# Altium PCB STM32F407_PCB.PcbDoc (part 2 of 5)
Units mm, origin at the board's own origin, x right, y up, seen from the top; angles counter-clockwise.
Board outline 100.27 x 100.27 mm, 2 copper layers (Top Layer, Bottom Layer); 134 components, 132 nets, 659 pads, 288 vias.
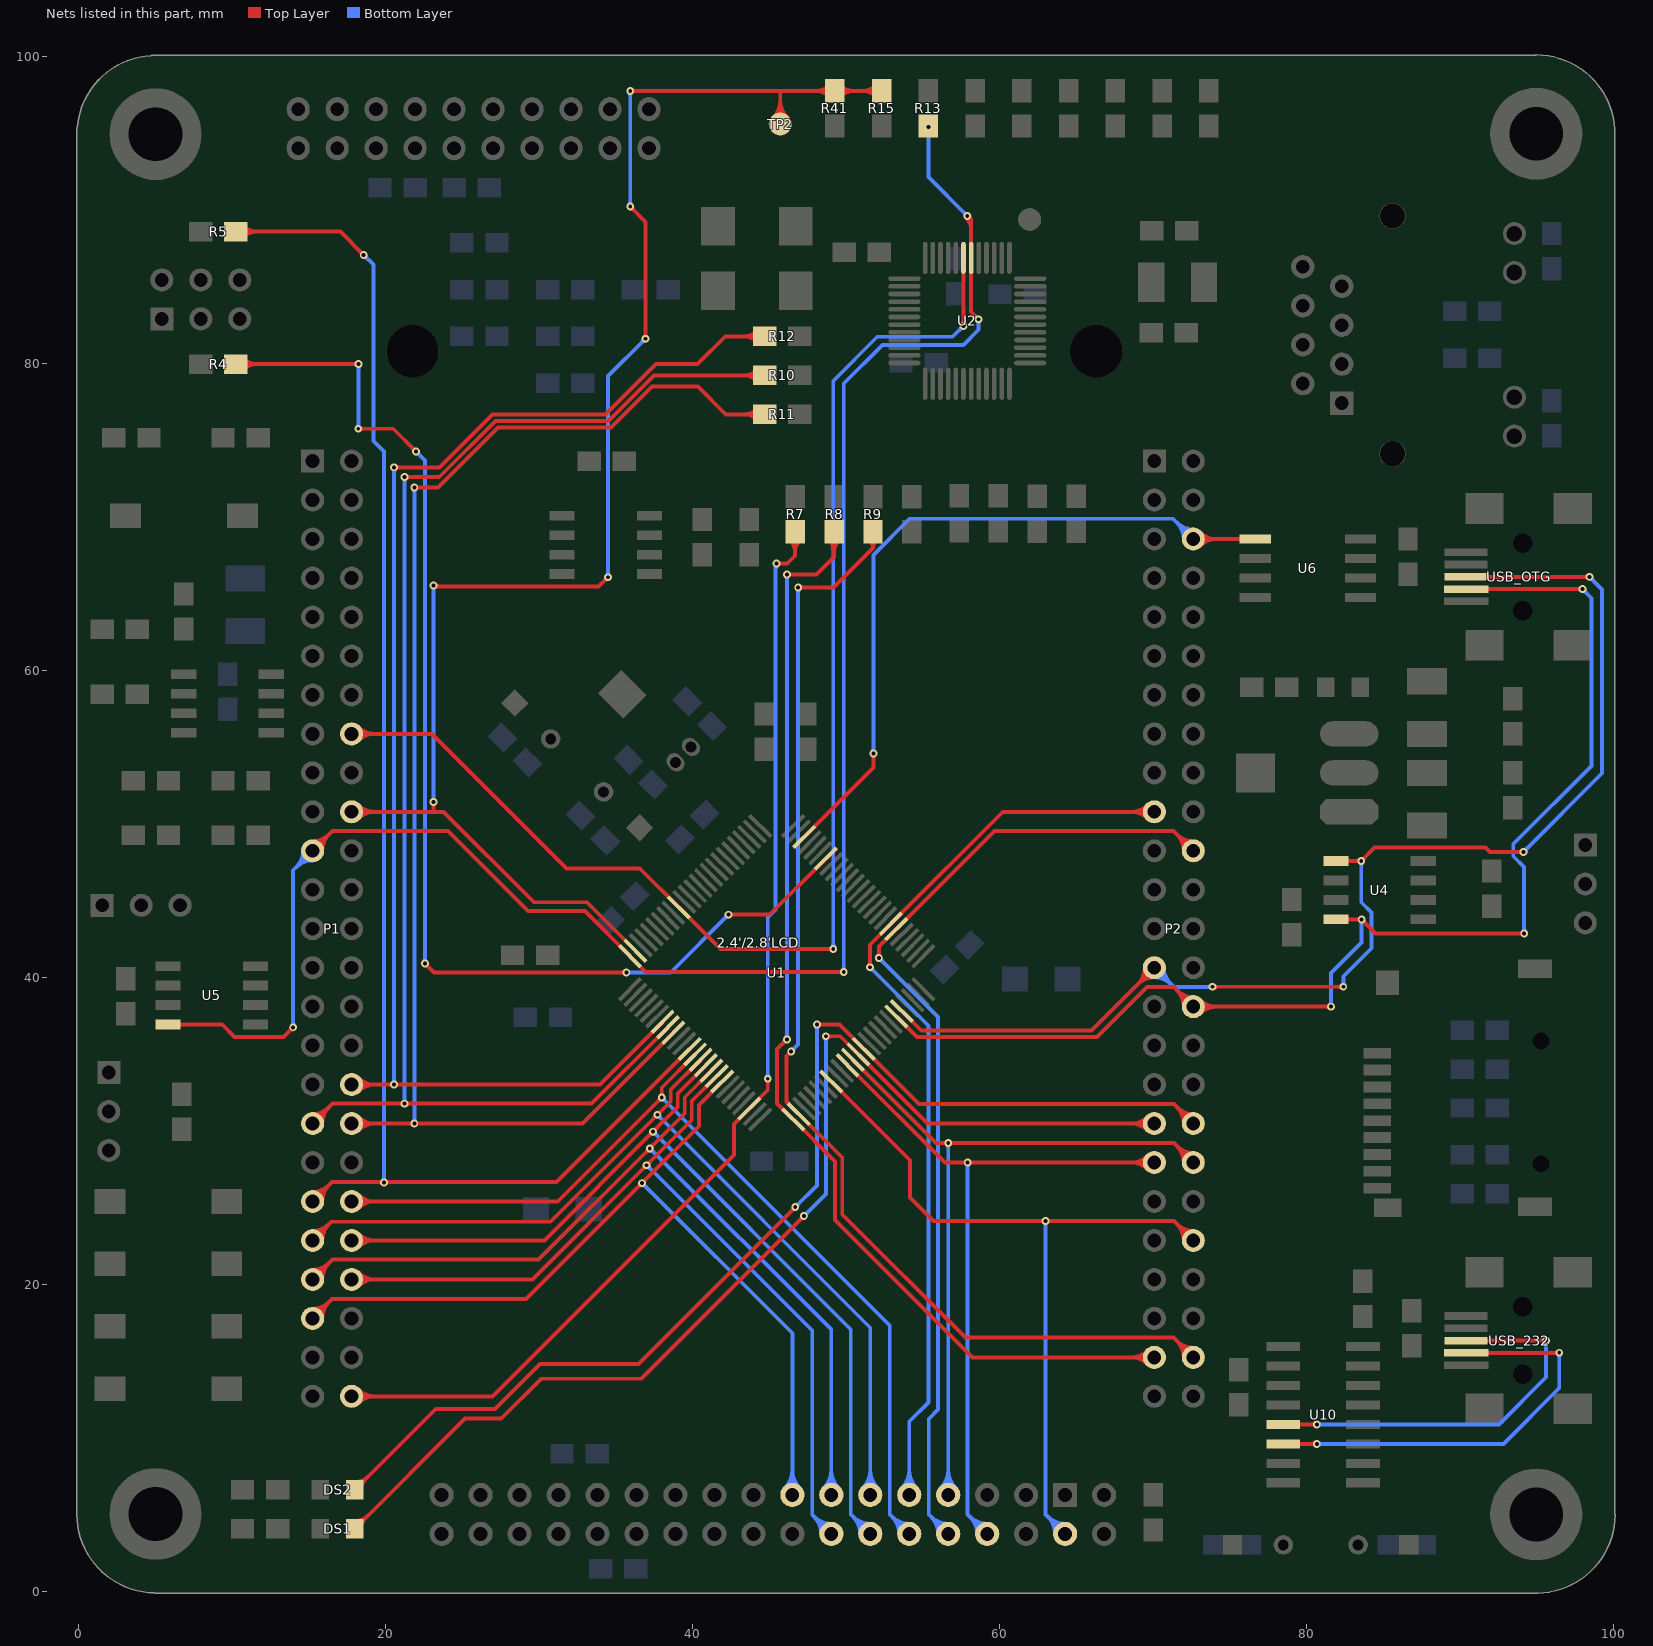
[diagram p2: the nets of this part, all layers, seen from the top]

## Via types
v1: diameter 0.508, hole 0.254, Top Layer to Bottom Layer, 288 vias

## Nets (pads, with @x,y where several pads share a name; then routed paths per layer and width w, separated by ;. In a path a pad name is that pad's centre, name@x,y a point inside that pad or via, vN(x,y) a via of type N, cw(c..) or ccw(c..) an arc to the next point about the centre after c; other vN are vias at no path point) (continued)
BOOT0: R4.2 U1.94 | length 94.7
  Top Layer w0.254: R4.2@10.236,79.983 v1(18.237,79.983) ; v1(18.212,75.768) 20.498,75.768 v1(21.984,74.282) ; v1(22.555,40.919) 23.139,40.335 v1(35.687,40.335) ; v1(42.342,44.094) 45.033,44.094 U1.94@48.691,47.752 ; 11.59,79.983 cw(c11.59,81.209) 10.722,80.342 ccw(c11.59,81.209) 11.59,79.983 ; 11.59,79.983 ccw(c11.59,78.757) 10.722,79.624 cw(c11.59,78.757) 11.59,79.983 ; 17.931,79.983 cw(c17.931,79.676) 18.147,79.893 ccw(c17.931,79.676) 17.931,79.983 ; 17.931,79.983 ccw(c17.931,80.29) 18.147,80.073 cw(c17.931,80.29) 17.931,79.983 ; 18.518,75.768 cw(c18.518,76.075) 18.302,75.858 ccw(c18.518,76.075) 18.518,75.768 ; 18.518,75.768 ccw(c18.518,75.462) 18.302,75.678 cw(c18.518,75.462) 18.518,75.768 ; 21.767,74.499 cw(c21.55,74.282) 21.857,74.282 ccw(c21.55,74.282) 21.767,74.499 ; 21.767,74.499 ccw(c21.984,74.716) 21.984,74.409 cw(c21.984,74.716) 21.767,74.499 ; 22.772,40.703 cw(c22.989,40.919) 22.682,40.919 ccw(c22.989,40.919) 22.772,40.703 ; 22.772,40.703 ccw(c22.555,40.486) 22.555,40.792 cw(c22.555,40.486) 22.772,40.703 ; 35.38,40.335 cw(c35.38,40.029) 35.597,40.245 ccw(c35.38,40.029) 35.38,40.335 ; 35.38,40.335 ccw(c35.38,40.642) 35.597,40.425 cw(c35.38,40.642) 35.38,40.335 ; 42.648,44.094 cw(c42.648,44.401) 42.432,44.184 ccw(c42.648,44.401) 42.648,44.094 ; 42.648,44.094 ccw(c42.648,43.788) 42.432,44.005 cw(c42.648,43.788) 42.648,44.094
  Bottom Layer w0.254: v1(18.212,75.768) 18.237,75.794 v1(18.237,79.983) ; v1@21.971,74.295 v1(21.984,74.282) 22.555,73.711 v1(22.555,40.919) ; v1(35.687,40.335) 38.583,40.335 v1(42.342,44.094) ; 18.237,79.676 cw(c18.544,79.676) 18.327,79.893 ccw(c18.544,79.676) 18.237,79.676 ; 18.237,79.676 ccw(c17.931,79.676) 18.147,79.893 cw(c17.931,79.676) 18.237,79.676 ; 22.201,74.065 cw(c22.417,74.282) 22.111,74.282 ccw(c22.417,74.282) 22.201,74.065 ; 22.201,74.065 ccw(c21.984,73.849) 21.984,74.155 cw(c21.984,73.849) 22.201,74.065 ; 22.555,41.226 cw(c22.249,41.226) 22.465,41.009 ccw(c22.249,41.226) 22.555,41.226 ; 22.555,41.226 ccw(c22.862,41.226) 22.645,41.009 cw(c22.862,41.226) 22.555,41.226 ; 35.994,40.335 cw(c35.994,40.642) 35.777,40.425 ccw(c35.994,40.642) 35.994,40.335 ; 35.994,40.335 ccw(c35.994,40.029) 35.777,40.245 cw(c35.994,40.029) 35.994,40.335 ; 42.125,43.878 cw(c42.342,43.661) 42.342,43.967 ccw(c42.342,43.661) 42.125,43.878 ; 42.125,43.878 ccw(c41.908,44.094) 42.215,44.094 cw(c41.908,44.094) 42.125,43.878 ; v1@18.122,75.858 ccw(c17.844,76.136) 18.237,76.136 cw(c17.844,76.136) v1@18.122,75.858
BOOT1: P1.39 R5.2 U1.37 | length 114.2
  Top Layer w0.254: R5.2@10.236,88.619 17.045,88.619 v1(18.567,87.097) ; P1.39@15.24,25.4 16.51,26.67 31.145,26.67 U1.37@39.817,35.342 ; 11.59,88.619 cw(c11.59,89.845) 10.722,88.978 ccw(c11.59,89.845) 11.59,88.619 ; 11.59,88.619 ccw(c11.59,87.393) 10.722,88.26 cw(c11.59,87.393) 11.59,88.619 ; 15.87,26.03 cw(c15.24,26.66) 15.24,25.769 ccw(c15.24,26.66) 15.87,26.03 ; 15.87,26.03 ccw(c16.5,25.4) 15.609,25.4 cw(c16.5,25.4) 15.87,26.03 ; 16.304,26.464 cw(c15.24,27.527) 15.24,26.023 ccw(c15.24,27.527) 16.304,26.464 ; 16.304,26.464 ccw(c17.367,25.4) 15.863,25.4 cw(c17.367,25.4) 16.304,26.464 ; 18.351,87.313 cw(c18.134,87.097) 18.44,87.097 ccw(c18.134,87.097) 18.351,87.313 ; 18.351,87.313 ccw(c18.567,87.53) 18.567,87.224 cw(c18.567,87.53) 18.351,87.313 ; 19.52,26.67 cw(c19.52,26.277) 19.798,26.555 ccw(c19.52,26.277) 19.52,26.67 ; v1@19.978,26.555 cw(c20.256,26.277) 20.256,26.67 ccw(c20.256,26.277) v1@19.978,26.555
  Bottom Layer w0.254: v1(18.567,87.097) 19.202,86.462 19.202,74.981 19.888,74.295 v1(19.888,26.645) ; 18.784,86.88 cw(c19.001,87.097) 18.694,87.097 ccw(c19.001,87.097) 18.784,86.88 ; 18.784,86.88 ccw(c18.567,86.663) 18.567,86.97 cw(c18.567,86.663) 18.784,86.88 ; 19.888,26.951 cw(c19.582,26.951) 19.798,26.734 ccw(c19.582,26.951) 19.888,26.951 ; 19.888,26.951 ccw(c20.195,26.951) 19.978,26.734 cw(c20.195,26.951) 19.888,26.951
CAN_RX: P2.30 U1.70 U4.4 USB_OTG.2 | length 108.7
  Top Layer w0.254: U1.70@53.287,37.464 54.632,36.119 66.37,36.119 69.621,39.37 71.374,39.37 P2.30@72.644,38.1 v1(81.61,38.1) ; U4.4@81.94,43.79 v1(83.617,43.79) 84.531,42.875 v1(94.209,42.875) ; USB_OTG.2@90.424,65.316 v1(98.006,65.316) ; 71.58,39.164 cw(c70.517,38.1) 72.021,38.1 ccw(c70.517,38.1) 71.58,39.164 ; 71.58,39.164 ccw(c72.644,40.227) 72.644,38.723 cw(c72.644,40.227) 71.58,39.164 ; 72.014,38.73 cw(c71.384,38.1) 72.275,38.1 ccw(c71.384,38.1) 72.014,38.73 ; 72.014,38.73 ccw(c72.644,39.36) 72.644,38.469 cw(c72.644,39.36) 72.014,38.73 ; 73.535,38.1 cw(c73.535,38.991) 72.905,38.361 ccw(c73.535,38.991) 73.535,38.1 ; 73.535,38.1 ccw(c73.535,37.209) 72.905,37.839 cw(c73.535,37.209) 73.535,38.1 ; 74.148,38.1 cw(c74.148,39.604) 73.085,38.541 ccw(c74.148,39.604) 74.148,38.1 ; 74.148,38.1 ccw(c74.148,36.596) 73.085,37.659 cw(c74.148,36.596) 74.148,38.1 ; 81.304,38.1 cw(c81.304,37.793) 81.52,38.01 ccw(c81.304,37.793) 81.304,38.1 ; 81.304,38.1 ccw(c81.304,38.407) 81.52,38.19 cw(c81.304,38.407) 81.304,38.1 ; 82.908,43.79 cw(c82.908,44.25) 82.583,43.924 ccw(c82.908,44.25) 82.908,43.79 ; 82.908,43.79 ccw(c82.908,43.33) 82.583,43.655 cw(c82.908,43.33) 82.908,43.79 ; 83.31,43.79 cw(c83.31,43.483) 83.527,43.7 ccw(c83.31,43.483) 83.31,43.79 ; 83.31,43.79 ccw(c83.31,44.096) 83.527,43.879 cw(c83.31,44.096) 83.31,43.79 ; 83.834,43.573 cw(c84.05,43.79) 83.744,43.79 ccw(c84.05,43.79) 83.834,43.573 ; 83.834,43.573 ccw(c83.617,43.356) 83.617,43.663 cw(c83.617,43.356) 83.834,43.573 ; 91.921,65.316 cw(c91.921,65.613) 91.711,65.403 ccw(c91.921,65.613) 91.921,65.316 ; 91.921,65.316 ccw(c91.921,65.019) 91.711,65.229 cw(c91.921,65.019) 91.921,65.316 ; 93.902,42.875 cw(c93.902,42.569) 94.119,42.785 ccw(c93.902,42.569) 93.902,42.875 ; 93.902,42.875 ccw(c93.902,43.182) 94.119,42.965 cw(c93.902,43.182) 93.902,42.875 ; 97.699,65.316 cw(c97.699,65.009) 97.916,65.226 ccw(c97.699,65.009) 97.699,65.316 ; 97.699,65.316 ccw(c97.699,65.623) 97.916,65.406 cw(c97.699,65.623) 97.699,65.316
  Bottom Layer w0.254: v1(81.61,38.1) 81.61,40.284 83.617,42.291 v1(83.617,43.79) ; v1(94.209,42.875) 94.209,47.193 93.497,47.904 93.497,48.692 98.603,53.797 98.603,64.719 v1(98.006,65.316) ; 81.61,38.407 cw(c81.304,38.407) 81.52,38.19 ccw(c81.304,38.407) 81.61,38.407 ; 81.61,38.407 ccw(c81.917,38.407) 81.7,38.19 cw(c81.917,38.407) 81.61,38.407 ; 83.617,43.483 cw(c83.923,43.483) 83.707,43.7 ccw(c83.923,43.483) 83.617,43.483 ; 83.617,43.483 ccw(c83.31,43.483) 83.527,43.7 cw(c83.31,43.483) 83.617,43.483 ; 94.209,43.182 cw(c93.902,43.182) 94.119,42.965 ccw(c93.902,43.182) 94.209,43.182 ; 94.209,43.182 ccw(c94.515,43.182) 94.298,42.965 cw(c94.515,43.182) 94.209,43.182 ; 98.223,65.099 cw(c98.439,65.316) 98.133,65.316 ccw(c98.439,65.316) 98.223,65.099 ; 98.223,65.099 ccw(c98.006,64.882) 98.006,65.189 cw(c98.006,64.882) 98.223,65.099
CAN_TX: P2.27 U1.71 U4.1 USB_OTG.3 | length 109.6
  Top Layer w0.254: U1.71@53.641,37.817 54.907,36.551 66.015,36.551 P2.27@70.104,40.64 ; v1(73.889,39.395) v1(82.423,39.395) ; U4.1@81.94,47.6 v1(83.591,47.6) 84.455,48.463 91.694,48.463 91.973,48.184 v1(94.158,48.184) ; USB_OTG.3@90.424,66.116 v1(98.476,66.116) ; 69.04,39.576 cw(c70.104,38.513) 70.104,40.017 ccw(c70.104,38.513) 69.04,39.576 ; 69.04,39.576 ccw(c67.977,40.64) 69.481,40.64 cw(c67.977,40.64) 69.04,39.576 ; 69.474,40.01 cw(c70.104,39.38) 70.104,40.271 ccw(c70.104,39.38) 69.474,40.01 ; 69.474,40.01 ccw(c68.844,40.64) 69.735,40.64 cw(c68.844,40.64) 69.474,40.01 ; 74.195,39.395 cw(c74.195,39.702) 73.978,39.485 ccw(c74.195,39.702) 74.195,39.395 ; 74.195,39.395 ccw(c74.195,39.089) 73.978,39.306 cw(c74.195,39.089) 74.195,39.395 ; 82.116,39.395 cw(c82.116,39.089) 82.333,39.306 ccw(c82.116,39.089) 82.116,39.395 ; 82.116,39.395 ccw(c82.116,39.702) 82.333,39.485 cw(c82.116,39.702) 82.116,39.395 ; 82.908,47.6 cw(c82.908,48.06) 82.583,47.734 ccw(c82.908,48.06) 82.908,47.6 ; 82.908,47.6 ccw(c82.908,47.14) 82.583,47.465 cw(c82.908,47.14) 82.908,47.6 ; 83.285,47.6 cw(c83.285,47.293) 83.502,47.51 ccw(c83.285,47.293) 83.285,47.6 ; 83.285,47.6 ccw(c83.285,47.906) 83.502,47.689 cw(c83.285,47.906) 83.285,47.6 ; 83.808,47.816 cw(c83.591,48.033) 83.591,47.727 ccw(c83.591,48.033) 83.808,47.816 ; 83.808,47.816 ccw(c84.025,47.6) 83.718,47.6 cw(c84.025,47.6) 83.808,47.816 ; 91.871,66.116 cw(c91.871,66.413) 91.661,66.203 ccw(c91.871,66.413) 91.871,66.116 ; 91.871,66.116 ccw(c91.871,65.819) 91.661,66.029 cw(c91.871,65.819) 91.871,66.116 ; 93.851,48.184 cw(c93.851,47.877) 94.068,48.094 ccw(c93.851,47.877) 93.851,48.184 ; 93.851,48.184 ccw(c93.851,48.49) 94.068,48.274 cw(c93.851,48.49) 93.851,48.184 ; 98.169,66.116 cw(c98.169,65.809) 98.386,66.026 ccw(c98.169,65.809) 98.169,66.116 ; 98.169,66.116 ccw(c98.169,66.423) 98.386,66.206 cw(c98.169,66.423) 98.169,66.116
  Bottom Layer w0.254: P2.27@70.104,40.64 71.374,39.37 73.863,39.37 v1(73.889,39.395) ; v1(82.423,39.395) 82.423,40.081 84.252,41.91 84.252,44.247 83.591,44.907 v1(83.591,47.6) ; v1(94.158,48.184) 99.289,53.315 99.289,65.303 v1(98.476,66.116) ; 70.734,40.01 cw(c71.364,40.64) 70.473,40.64 ccw(c71.364,40.64) 70.734,40.01 ; 70.734,40.01 ccw(c70.104,39.38) 70.104,40.271 cw(c70.104,39.38) 70.734,40.01 ; 71.168,39.576 cw(c72.231,40.64) 70.727,40.64 ccw(c72.231,40.64) 71.168,39.576 ; 71.168,39.576 ccw(c70.104,38.513) 70.104,40.017 cw(c70.104,38.513) 71.168,39.576 ; 82.423,39.702 cw(c82.116,39.702) 82.333,39.485 ccw(c82.116,39.702) 82.423,39.702 ; 82.423,39.702 ccw(c82.73,39.702) 82.513,39.485 cw(c82.73,39.702) 82.423,39.702 ; 83.591,47.293 cw(c83.898,47.293) 83.681,47.51 ccw(c83.898,47.293) 83.591,47.293 ; 83.591,47.293 ccw(c83.285,47.293) 83.502,47.51 cw(c83.285,47.293) 83.591,47.293 ; 94.375,48.401 cw(c94.158,48.617) 94.158,48.311 ccw(c94.158,48.617) 94.375,48.401 ; 94.375,48.401 ccw(c94.591,48.184) 94.285,48.184 cw(c94.591,48.184) 94.375,48.401 ; 98.692,65.899 cw(c98.909,66.116) 98.603,66.116 ccw(c98.909,66.116) 98.692,65.899 ; 98.692,65.899 ccw(c98.476,65.682) 98.476,65.989 cw(c98.476,65.682) 98.692,65.899 ; 73.521,39.37 ccw(c73.521,39.763) 73.799,39.485 cw(c73.521,39.763) 73.521,39.37
CH340_D+: U10.5 USB_232.3 | length 32.1
  Top Layer w0.254: U10.5@78.502,10.871 v1(80.696,10.871) ; USB_232.3@90.424,16.332 v1(95.631,16.332) ; 79.72,10.871 cw(c79.72,11.289) 79.425,10.994 ccw(c79.72,11.289) 79.72,10.871 ; 79.72,10.871 ccw(c79.72,10.454) 79.425,10.749 cw(c79.72,10.454) 79.72,10.871 ; 80.389,10.871 cw(c80.389,10.565) 80.606,10.781 ccw(c80.389,10.565) 80.389,10.871 ; 80.389,10.871 ccw(c80.389,11.178) 80.606,10.961 cw(c80.389,11.178) 80.389,10.871 ; 91.871,16.332 cw(c91.871,16.629) 91.661,16.419 ccw(c91.871,16.629) 91.871,16.332 ; 91.871,16.332 ccw(c91.871,16.035) 91.661,16.245 cw(c91.871,16.035) 91.871,16.332 ; 95.325,16.332 cw(c95.325,16.025) 95.541,16.242 ccw(c95.325,16.025) 95.325,16.332 ; 95.325,16.332 ccw(c95.325,16.639) 95.541,16.422 cw(c95.325,16.639) 95.325,16.332
  Bottom Layer w0.254: v1(80.696,10.871) 92.558,10.871 95.631,13.945 v1(95.631,16.332) ; 81.002,10.871 cw(c81.002,11.178) 80.786,10.961 ccw(c81.002,11.178) 81.002,10.871 ; 81.002,10.871 ccw(c81.002,10.565) 80.786,10.781 cw(c81.002,10.565) 81.002,10.871 ; 95.631,16.025 cw(c95.938,16.025) 95.721,16.242 ccw(c95.938,16.025) 95.631,16.025 ; 95.631,16.025 ccw(c95.325,16.025) 95.541,16.242 cw(c95.325,16.025) 95.631,16.025
CH340_D-: U10.6 USB_232.2 | length 34
  Top Layer w0.254: U10.6@78.502,9.601 v1(80.696,9.601) ; USB_232.2@90.424,15.532 v1@96.495,15.532 ; 79.72,9.601 cw(c79.72,10.019) 79.425,9.724 ccw(c79.72,10.019) 79.72,9.601 ; 79.72,9.601 ccw(c79.72,9.184) 79.425,9.479 cw(c79.72,9.184) 79.72,9.601 ; 80.389,9.601 cw(c80.389,9.295) 80.606,9.511 ccw(c80.389,9.295) 80.389,9.601 ; 80.389,9.601 ccw(c80.389,9.908) 80.606,9.691 cw(c80.389,9.908) 80.389,9.601 ; 91.921,15.532 cw(c91.921,15.829) 91.711,15.619 ccw(c91.921,15.829) 91.921,15.532 ; 91.921,15.532 ccw(c91.921,15.235) 91.711,15.445 cw(c91.921,15.235) 91.921,15.532 ; 96.157,15.532 ccw(c96.157,15.882) 96.405,15.635 cw(c96.157,15.882) 96.157,15.532 ; 96.219,15.532 cw(c96.219,15.269) 96.405,15.455 ccw(c96.219,15.269) 96.219,15.532
  Bottom Layer w0.254: v1(80.696,9.601) 92.862,9.601 96.495,13.233 v1(96.495,15.545) ; 81.002,9.601 cw(c81.002,9.908) 80.786,9.691 ccw(c81.002,9.908) 81.002,9.601 ; 81.002,9.601 ccw(c81.002,9.295) 80.786,9.511 cw(c81.002,9.295) 81.002,9.601 ; 96.495,15.238 cw(c96.801,15.238) 96.584,15.455 ccw(c96.801,15.238) 96.495,15.238 ; 96.495,15.238 ccw(c96.188,15.238) 96.405,15.455 cw(c96.188,15.238) 96.495,15.238
DS1: DS1.2 P2.35 U1.63 | length 88.6
  Top Layer w0.254: DS1.2@17.983,4.064 25.171,11.252 27.534,11.252 30.124,13.843 36.652,13.843 v1(47.257,24.447) ; v1(48.692,36.17) 49.632,36.17 U1.63@50.812,34.989 55.321,30.48 P2.35@70.104,30.48 ; 47.04,24.231 cw(c47.257,24.014) 47.257,24.32 ccw(c47.257,24.014) 47.04,24.231 ; 47.04,24.231 ccw(c46.823,24.447) 47.13,24.447 cw(c46.823,24.447) 47.04,24.231 ; 48.998,36.17 cw(c48.998,36.476) 48.782,36.259 ccw(c48.998,36.476) 48.998,36.17 ; 48.998,36.17 ccw(c48.998,35.863) 48.782,36.08 cw(c48.998,35.863) 48.998,36.17 ; 68.6,30.48 cw(c68.6,28.976) 69.663,30.039 ccw(c68.6,28.976) 68.6,30.48 ; 68.6,30.48 ccw(c68.6,31.984) 69.663,30.921 cw(c68.6,31.984) 68.6,30.48 ; 69.213,30.48 cw(c69.213,29.589) 69.843,30.219 ccw(c69.213,29.589) 69.213,30.48 ; 69.213,30.48 ccw(c69.213,31.371) 69.843,30.741 cw(c69.213,31.371) 69.213,30.48 ; DS1.2@17.983,4.572 ccw(c17.983,5.798) 18.85,4.931 cw(c17.983,5.798) DS1.2@17.983,4.572 ; DS1.2@18.428,4.127 cw(c19.348,4.127) 18.697,4.778 ccw(c19.348,4.127) DS1.2@18.428,4.127
  Bottom Layer w0.254: v1(47.257,24.447) 48.692,25.883 v1(48.692,36.17) ; 47.474,24.664 cw(c47.257,24.881) 47.257,24.575 ccw(c47.257,24.881) 47.474,24.664 ; 47.474,24.664 ccw(c47.69,24.447) 47.384,24.447 cw(c47.69,24.447) 47.474,24.664 ; 48.692,35.863 cw(c48.998,35.863) 48.782,36.08 ccw(c48.998,35.863) 48.692,35.863 ; 48.692,35.863 ccw(c48.385,35.863) 48.602,36.08 cw(c48.385,35.863) 48.692,35.863
DS2: DS2.2 P2.36 U1.64 | length 90.8
  Top Layer w0.254: DS2.2@17.983,6.604 23.266,11.887 27.127,11.887 30.048,14.808 36.474,14.808 v1@46.711,25.044 ; v1(48.108,36.932) 49.577,36.932 U1.64@51.166,35.342 54.758,31.75 71.374,31.75 P2.36@72.644,30.48 ; 46.481,24.815 cw(c46.698,24.598) 46.698,24.905 ccw(c46.698,24.598) 46.481,24.815 ; 46.481,24.815 ccw(c46.264,25.032) 46.571,25.032 cw(c46.264,25.032) 46.481,24.815 ; 48.414,36.932 cw(c48.414,37.238) 48.197,37.021 ccw(c48.414,37.238) 48.414,36.932 ; 48.414,36.932 ccw(c48.414,36.625) 48.197,36.842 cw(c48.414,36.625) 48.414,36.932 ; 71.58,31.544 cw(c70.517,30.48) 72.021,30.48 ccw(c70.517,30.48) 71.58,31.544 ; 71.58,31.544 ccw(c72.644,32.607) 72.644,31.103 cw(c72.644,32.607) 71.58,31.544 ; 72.014,31.11 cw(c71.384,30.48) 72.275,30.48 ccw(c71.384,30.48) 72.014,31.11 ; 72.014,31.11 ccw(c72.644,31.74) 72.644,30.849 cw(c72.644,31.74) 72.014,31.11 ; DS2.2@17.983,7.112 ccw(c17.983,8.338) 18.85,7.471 cw(c17.983,8.338) DS2.2@17.983,7.112 ; DS2.2@18.428,6.667 cw(c19.348,6.667) 18.697,7.318 ccw(c19.348,6.667) DS2.2@18.428,6.667
  Bottom Layer w0.254: v1(46.698,25.032) 48.108,26.441 v1(48.108,36.932) ; 46.915,25.249 cw(c46.698,25.465) 46.698,25.159 ccw(c46.698,25.465) 46.915,25.249 ; 46.915,25.249 ccw(c47.132,25.032) 46.825,25.032 cw(c47.132,25.032) 46.915,25.249 ; 48.108,36.625 cw(c48.414,36.625) 48.197,36.842 ccw(c48.414,36.625) 48.108,36.625 ; 48.108,36.625 ccw(c47.801,36.625) 48.018,36.842 cw(c47.801,36.625) 48.108,36.625
ETH_MDC: P1.16 U1.16 U2.31 | length 100
  Top Layer w0.254: P1.16@17.78,55.88 23.012,55.88 31.775,47.117 36.563,47.117 U1.16@39.11,44.57 41.821,41.859 v1(49.174,41.859) ; v1(57.658,82.474) 57.662,82.478 U2.31@57.662,86.904 ; 18.671,55.88 cw(c18.671,56.771) 18.041,56.141 ccw(c18.671,56.771) 18.671,55.88 ; 18.671,55.88 ccw(c18.671,54.989) 18.041,55.619 cw(c18.671,54.989) 18.671,55.88 ; 19.284,55.88 cw(c19.284,57.384) 18.221,56.321 ccw(c19.284,57.384) 19.284,55.88 ; 19.284,55.88 ccw(c19.284,54.376) 18.221,55.439 cw(c19.284,54.376) 19.284,55.88 ; 48.868,41.859 cw(c48.868,41.553) 49.085,41.769 ccw(c48.868,41.553) 48.868,41.859 ; 48.868,41.859 ccw(c48.868,42.166) 49.085,41.949 cw(c48.868,42.166) 48.868,41.859 ; v1@57.568,82.564 ccw(c57.342,82.79) 57.662,82.79 cw(c57.342,82.79) v1@57.568,82.564 ; 57.662,82.771 ccw(c57.955,82.771) 57.748,82.564 cw(c57.955,82.771) 57.662,82.771
  Bottom Layer w0.254: v1(49.174,41.859) 49.174,78.892 52.045,81.763 56.947,81.763 v1(57.658,82.474) ; 49.174,42.166 cw(c48.868,42.166) 49.085,41.949 ccw(c48.868,42.166) 49.174,42.166 ; 49.174,42.166 ccw(c49.481,42.166) 49.264,41.949 cw(c49.481,42.166) 49.174,42.166 ; 57.441,82.257 cw(c57.658,82.04) 57.658,82.347 ccw(c57.658,82.04) 57.441,82.257 ; 57.441,82.257 ccw(c57.224,82.474) 57.531,82.474 cw(c57.224,82.474) 57.441,82.257
ETH_MDIO: P1.21 R13.1 U1.25 U2.30 U5.4 | length 149.8
  Top Layer w0.254: U5.4@5.817,36.932 9.347,36.932 10.16,36.119 13.335,36.119 v1(13.97,36.754) ; P1.21@15.24,48.26 16.535,49.555 24.054,49.555 29.286,44.323 32.993,44.323 U1.25@35.928,41.388 36.955,40.361 v1(49.86,40.361) ; v1(57.912,89.637) 58.162,89.387 U2.30@58.162,86.904 58.162,83.392 v1(58.649,82.906) ; 6.785,36.932 cw(c6.785,37.392) 6.459,37.066 ccw(c6.785,37.392) 6.785,36.932 ; 6.785,36.932 ccw(c6.785,36.472) 6.459,36.797 cw(c6.785,36.472) 6.785,36.932 ; 13.753,36.537 cw(c13.97,36.32) 13.97,36.627 ccw(c13.97,36.32) 13.753,36.537 ; 13.753,36.537 ccw(c13.536,36.754) 13.843,36.754 cw(c13.536,36.754) 13.753,36.537 ; 15.87,48.89 cw(c15.24,49.52) 15.24,48.629 ccw(c15.24,49.52) 15.87,48.89 ; 15.87,48.89 ccw(c16.5,48.26) 15.609,48.26 cw(c16.5,48.26) 15.87,48.89 ; 16.304,49.324 cw(c15.24,50.387) 15.24,48.883 ccw(c15.24,50.387) 16.304,49.324 ; 16.304,49.324 ccw(c17.367,48.26) 15.863,48.26 cw(c17.367,48.26) 16.304,49.324 ; 49.554,40.361 cw(c49.554,40.054) 49.77,40.271 ccw(c49.554,40.054) 49.554,40.361 ; 49.554,40.361 ccw(c49.554,40.667) 49.77,40.45 cw(c49.554,40.667) 49.554,40.361 ; 58.432,83.122 cw(c58.215,82.906) 58.522,82.906 ccw(c58.215,82.906) 58.432,83.122 ; 58.432,83.122 ccw(c58.649,83.339) 58.649,83.033 cw(c58.649,83.339) 58.432,83.122 ; v1@57.822,89.547 cw(c57.002,88.726) 58.162,88.726 ccw(c57.002,88.726) v1@57.822,89.547 ; v1@58.002,89.726 cw(c57.615,89.34) 58.162,89.34 ccw(c57.615,89.34) v1@58.002,89.726
  Bottom Layer w0.254: v1(13.97,36.754) 13.97,46.99 P1.21@15.24,48.26 ; v1(49.86,40.361) 49.86,78.715 52.375,81.229 57.658,81.229 58.649,82.22 v1(58.649,82.906) ; v1(55.372,95.428) 55.372,92.177 v1(57.912,89.637) ; 13.97,37.06 cw(c13.663,37.06) 13.88,36.844 ccw(c13.663,37.06) 13.97,37.06 ; 13.97,37.06 ccw(c14.277,37.06) 14.06,36.844 cw(c14.277,37.06) 13.97,37.06 ; 14.176,47.196 cw(c15.24,46.133) 15.24,47.637 ccw(c15.24,46.133) 14.176,47.196 ; 14.176,47.196 ccw(c13.113,48.26) 14.617,48.26 cw(c13.113,48.26) 14.176,47.196 ; 14.61,47.63 cw(c15.24,47) 15.24,47.891 ccw(c15.24,47) 14.61,47.63 ; 14.61,47.63 ccw(c13.98,48.26) 14.871,48.26 cw(c13.98,48.26) 14.61,47.63 ; 49.86,40.667 cw(c49.554,40.667) 49.77,40.45 ccw(c49.554,40.667) 49.86,40.667 ; 49.86,40.667 ccw(c50.167,40.667) 49.95,40.45 cw(c50.167,40.667) 49.86,40.667 ; 55.372,95.121 cw(c55.679,95.121) 55.462,95.338 ccw(c55.679,95.121) 55.372,95.121 ; 55.372,95.121 ccw(c55.065,95.121) 55.282,95.338 cw(c55.065,95.121) 55.372,95.121 ; 57.695,89.853 cw(c57.478,89.637) 57.785,89.637 ccw(c57.478,89.637) 57.695,89.853 ; 57.695,89.853 ccw(c57.912,90.07) 57.912,89.764 cw(c57.912,90.07) 57.695,89.853 ; 58.649,82.599 cw(c58.955,82.599) 58.738,82.816 ccw(c58.955,82.599) 58.649,82.599 ; 58.649,82.599 ccw(c58.342,82.599) 58.559,82.816 cw(c58.342,82.599) 58.649,82.599
ETH_R_CLK: P1.20 R15.2 R41.2 TP2.1 U1.24 | length 134.7
  Top Layer w0.254: P1.20@17.78,50.8 23.114,50.8 ; v1(23.114,51.435) 23.114,50.8 ; v1(23.114,65.557) 23.19,65.481 33.884,65.481 v1(34.493,66.091) ; v1(35.941,90.246) 36.932,89.256 v1(36.932,81.636) ; v1(35.941,97.79) 45.669,97.79 ; U1.24@36.281,41.742 33.116,44.907 29.667,44.907 23.774,50.8 23.114,50.8 ; TP2.1@45.279,96.072 ccw(c44.216,97.135) 45.72,97.135 ccw(c47.224,97.135) TP2.1@46.161,96.072 ; TP2.1@45.459,95.892 ccw(c44.829,96.522) 45.72,96.522 ccw(c46.611,96.522) TP2.1@45.981,95.892 ; TP2.1@45.72,95.631 45.72,97.739 45.669,97.79 ; R15.2@52.326,97.79 R41.2@49.278,97.79 45.669,97.79 ; 18.671,50.8 cw(c18.671,51.691) 18.041,51.061 ccw(c18.671,51.691) 18.671,50.8 ; 18.671,50.8 ccw(c18.671,49.909) 18.041,50.539 cw(c18.671,49.909) 18.671,50.8 ; 19.284,50.8 cw(c19.284,52.304) 18.221,51.241 ccw(c19.284,52.304) 19.284,50.8 ; 19.284,50.8 ccw(c19.284,49.296) 18.221,50.359 cw(c19.284,49.296) 19.284,50.8 ; 23.114,51.128 cw(c23.421,51.128) 23.204,51.345 ccw(c23.421,51.128) 23.114,51.128 ; 23.114,51.128 ccw(c22.807,51.128) 23.024,51.345 cw(c22.807,51.128) 23.114,51.128 ; 34.276,65.874 cw(c34.493,65.657) 34.493,65.964 ccw(c34.493,65.657) 34.276,65.874 ; 34.276,65.874 ccw(c34.06,66.091) 34.366,66.091 cw(c34.06,66.091) 34.276,65.874 ; 36.158,90.029 cw(c36.375,90.246) 36.068,90.246 ccw(c36.375,90.246) 36.158,90.029 ; 36.158,90.029 ccw(c35.941,89.813) 35.941,90.119 cw(c35.941,89.813) 36.158,90.029 ; 36.248,97.79 cw(c36.248,98.097) 36.031,97.88 ccw(c36.248,98.097) 36.248,97.79 ; 36.248,97.79 ccw(c36.248,97.483) 36.031,97.7 cw(c36.248,97.483) 36.248,97.79 ; 36.932,81.942 cw(c36.625,81.942) 36.842,81.725 ccw(c36.625,81.942) 36.932,81.942 ; 36.932,81.942 ccw(c37.238,81.942) 37.021,81.725 cw(c37.238,81.942) 36.932,81.942 ; 48.051,97.79 cw(c48.051,96.564) 48.918,97.431 ccw(c48.051,96.564) 48.051,97.79 ; 48.051,97.79 ccw(c48.051,99.016) 48.918,98.149 cw(c48.051,99.016) 48.051,97.79 ; 50.504,97.79 cw(c50.504,99.016) 49.637,98.149 ccw(c50.504,99.016) 50.504,97.79 ; 50.504,97.79 ccw(c50.504,96.564) 49.637,97.431 cw(c50.504,96.564) 50.504,97.79 ; 51.099,97.79 cw(c51.099,96.564) 51.966,97.431 ccw(c51.099,96.564) 51.099,97.79 ; 51.099,97.79 ccw(c51.099,99.016) 51.966,98.149 cw(c51.099,99.016) 51.099,97.79 ; v1@23.204,65.647 ccw(c23.605,66.048) 23.605,65.481 cw(c23.605,66.048) v1@23.204,65.647
  Bottom Layer w0.254: v1(23.114,51.435) v1(23.114,65.557) ; v1(34.493,66.091) 34.493,79.197 v1(36.932,81.636) ; v1(35.941,90.246) v1(35.941,97.79) ; 23.114,51.742 cw(c22.807,51.742) 23.024,51.525 ccw(c22.807,51.742) 23.114,51.742 ; 23.114,51.742 ccw(c23.421,51.742) 23.204,51.525 cw(c23.421,51.742) 23.114,51.742 ; 23.114,65.251 cw(c23.421,65.251) 23.204,65.468 ccw(c23.421,65.251) 23.114,65.251 ; 23.114,65.251 ccw(c22.807,65.251) 23.024,65.468 cw(c22.807,65.251) 23.114,65.251 ; 34.493,66.397 cw(c34.187,66.397) 34.403,66.181 ccw(c34.187,66.397) 34.493,66.397 ; 34.493,66.397 ccw(c34.8,66.397) 34.583,66.181 cw(c34.8,66.397) 34.493,66.397 ; 35.941,90.553 cw(c35.634,90.553) 35.851,90.336 ccw(c35.634,90.553) 35.941,90.553 ; 35.941,90.553 ccw(c36.248,90.553) 36.031,90.336 cw(c36.248,90.553) 35.941,90.553 ; 35.941,97.483 cw(c36.248,97.483) 36.031,97.7 ccw(c36.248,97.483) 35.941,97.483 ; 35.941,97.483 ccw(c35.634,97.483) 35.851,97.7 cw(c35.634,97.483) 35.941,97.483 ; 36.715,81.419 cw(c36.932,81.202) 36.932,81.509 ccw(c36.932,81.202) 36.715,81.419 ; 36.715,81.419 ccw(c36.498,81.636) 36.805,81.636 cw(c36.498,81.636) 36.715,81.419
ETH_RXD0: P1.35 R10.1 U1.33 | length 109
  Top Layer w0.254: P1.35@15.24,30.48 16.535,31.775 33.421,31.775 U1.33@38.403,36.757 ; v1(21.234,72.619) 23.496,72.619 27.154,76.276 34.513,76.276 37.483,79.246 R10.1@44.704,79.246 ; 15.87,31.11 cw(c15.24,31.74) 15.24,30.849 ccw(c15.24,31.74) 15.87,31.11 ; 15.87,31.11 ccw(c16.5,30.48) 15.609,30.48 cw(c16.5,30.48) 15.87,31.11 ; 16.304,31.544 cw(c15.24,32.607) 15.24,31.103 ccw(c15.24,32.607) 16.304,31.544 ; 16.304,31.544 ccw(c17.367,30.48) 15.863,30.48 cw(c17.367,30.48) 16.304,31.544 ; 20.928,31.775 cw(c20.928,31.469) 21.145,31.686 ccw(c20.928,31.469) 20.928,31.775 ; 20.928,31.775 ccw(c20.928,32.082) 21.145,31.865 cw(c20.928,32.082) 20.928,31.775 ; 21.541,31.775 cw(c21.541,32.082) 21.324,31.865 ccw(c21.541,32.082) 21.541,31.775 ; 21.541,31.775 ccw(c21.541,31.469) 21.324,31.686 cw(c21.541,31.469) 21.541,31.775 ; 21.541,72.619 cw(c21.541,72.925) 21.324,72.708 ccw(c21.541,72.925) 21.541,72.619 ; 21.541,72.619 ccw(c21.541,72.312) 21.324,72.529 cw(c21.541,72.312) 21.541,72.619 ; 43.351,79.246 cw(c43.351,78.02) 44.218,78.887 ccw(c43.351,78.02) 43.351,79.246 ; 43.351,79.246 ccw(c43.351,80.473) 44.218,79.606 cw(c43.351,80.473) 43.351,79.246
  Bottom Layer w0.254: v1(21.234,31.775) v1(21.234,72.619) ; 21.234,32.082 cw(c20.928,32.082) 21.145,31.865 ccw(c20.928,32.082) 21.234,32.082 ; 21.234,32.082 ccw(c21.541,32.082) 21.324,31.865 cw(c21.541,32.082) 21.234,32.082 ; 21.234,72.312 cw(c21.541,72.312) 21.324,72.529 ccw(c21.541,72.312) 21.234,72.312 ; 21.234,72.312 ccw(c20.928,72.312) 21.145,72.529 cw(c20.928,72.312) 21.234,72.312
ETH_RXD1: P1.36 R11.1 U1.34 | length 107.4
  Top Layer w0.254: P1.36@17.78,30.48 32.833,30.48 U1.34@38.756,36.403 ; v1(21.869,71.933) 23.421,71.933 27.333,75.844 34.692,75.844 37.359,78.511 40.361,78.511 42.166,76.706 R11.1@44.704,76.706 ; 18.671,30.48 cw(c18.671,31.371) 18.041,30.741 ccw(c18.671,31.371) 18.671,30.48 ; 18.671,30.48 ccw(c18.671,29.589) 18.041,30.219 cw(c18.671,29.589) 18.671,30.48 ; 19.284,30.48 cw(c19.284,31.984) 18.221,30.921 ccw(c19.284,31.984) 19.284,30.48 ; 19.284,30.48 ccw(c19.284,28.976) 18.221,30.039 cw(c19.284,28.976) 19.284,30.48 ; 21.563,30.48 cw(c21.563,30.173) 21.78,30.39 ccw(c21.563,30.173) 21.563,30.48 ; 21.563,30.48 ccw(c21.563,30.787) 21.78,30.57 cw(c21.563,30.787) 21.563,30.48 ; 22.176,30.48 cw(c22.176,30.787) 21.959,30.57 ccw(c22.176,30.787) 22.176,30.48 ; 22.176,30.48 ccw(c22.176,30.173) 21.959,30.39 cw(c22.176,30.173) 22.176,30.48 ; 22.176,71.933 cw(c22.176,72.239) 21.959,72.023 ccw(c22.176,72.239) 22.176,71.933 ; 22.176,71.933 ccw(c22.176,71.626) 21.959,71.843 cw(c22.176,71.626) 22.176,71.933 ; 43.351,76.706 cw(c43.351,75.48) 44.218,76.347 ccw(c43.351,75.48) 43.351,76.706 ; 43.351,76.706 ccw(c43.351,77.933) 44.218,77.066 cw(c43.351,77.933) 43.351,76.706
  Bottom Layer w0.254: v1(21.869,30.48) v1(21.869,71.933) ; 21.869,30.787 cw(c21.563,30.787) 21.78,30.57 ccw(c21.563,30.787) 21.869,30.787 ; 21.869,30.787 ccw(c22.176,30.787) 21.959,30.57 cw(c22.176,30.787) 21.869,30.787 ; 21.869,71.626 cw(c22.176,71.626) 21.959,71.843 ccw(c22.176,71.626) 21.869,71.626 ; 21.869,71.626 ccw(c21.563,71.626) 21.78,71.843 cw(c21.563,71.626) 21.869,71.626
ETH_RXDV: P1.34 R12.1 U1.32 | length 106.1
  Top Layer w0.254: P1.34@17.78,33.02 33.959,33.02 U1.32@38.049,37.11 ; v1(20.549,73.254) 23.52,73.254 26.975,76.708 34.334,76.708 37.611,79.985 40.335,79.985 42.137,81.786 R12.1@44.704,81.786 ; 18.671,33.02 cw(c18.671,33.911) 18.041,33.281 ccw(c18.671,33.911) 18.671,33.02 ; 18.671,33.02 ccw(c18.671,32.129) 18.041,32.759 cw(c18.671,32.129) 18.671,33.02 ; 19.284,33.02 cw(c19.284,34.524) 18.221,33.461 ccw(c19.284,34.524) 19.284,33.02 ; 19.284,33.02 ccw(c19.284,31.516) 18.221,32.579 cw(c19.284,31.516) 19.284,33.02 ; 20.242,33.02 cw(c20.242,32.713) 20.459,32.93 ccw(c20.242,32.713) 20.242,33.02 ; 20.242,33.02 ccw(c20.242,33.327) 20.459,33.11 cw(c20.242,33.327) 20.242,33.02 ; 20.855,33.02 cw(c20.855,33.327) 20.638,33.11 ccw(c20.855,33.327) 20.855,33.02 ; 20.855,33.02 ccw(c20.855,32.713) 20.638,32.93 cw(c20.855,32.713) 20.855,33.02 ; 20.855,73.254 cw(c20.855,73.56) 20.638,73.343 ccw(c20.855,73.56) 20.855,73.254 ; 20.855,73.254 ccw(c20.855,72.947) 20.638,73.164 cw(c20.855,72.947) 20.855,73.254 ; 43.351,81.786 cw(c43.351,80.56) 44.218,81.427 ccw(c43.351,80.56) 43.351,81.786 ; 43.351,81.786 ccw(c43.351,83.013) 44.218,82.146 cw(c43.351,83.013) 43.351,81.786
  Bottom Layer w0.254: v1(20.549,33.02) v1(20.549,73.254) ; 20.549,33.327 cw(c20.242,33.327) 20.459,33.11 ccw(c20.242,33.327) 20.549,33.327 ; 20.549,33.327 ccw(c20.855,33.327) 20.638,33.11 cw(c20.855,33.327) 20.549,33.327 ; 20.549,72.947 cw(c20.855,72.947) 20.638,73.164 ccw(c20.855,72.947) 20.549,72.947 ; 20.549,72.947 ccw(c20.242,72.947) 20.459,73.164 cw(c20.242,72.947) 20.549,72.947
ETH_TXD0: P2.47 R8.1 U1.51 | length 88.9
  Top Layer w0.254: v1(46.152,35.966) 45.517,35.331 45.517,31.799 U1.51@46.57,30.746 49.301,28.015 49.301,24.181 58.242,15.24 P2.47@70.104,15.24 ; v1(46.152,66.269) 48.082,66.269 49.225,67.412 R8.1@49.225,69.063 ; 45.935,35.75 cw(c46.152,35.533) 46.152,35.839 ccw(c46.152,35.533) 45.935,35.75 ; 45.935,35.75 ccw(c45.718,35.966) 46.025,35.966 cw(c45.718,35.966) 45.935,35.75 ; 46.458,66.269 cw(c46.458,66.575) 46.242,66.358 ccw(c46.458,66.575) 46.458,66.269 ; 46.458,66.269 ccw(c46.458,65.962) 46.242,66.179 cw(c46.458,65.962) 46.458,66.269 ; 49.225,67.709 cw(c50.452,67.709) 49.584,68.576 ccw(c50.452,67.709) 49.225,67.709 ; 49.225,67.709 ccw(c47.999,67.709) 48.866,68.576 cw(c47.999,67.709) 49.225,67.709 ; 68.6,15.24 cw(c68.6,13.736) 69.663,14.799 ccw(c68.6,13.736) 68.6,15.24 ; 68.6,15.24 ccw(c68.6,16.744) 69.663,15.681 cw(c68.6,16.744) 68.6,15.24 ; 69.213,15.24 cw(c69.213,14.349) 69.843,14.979 ccw(c69.213,14.349) 69.213,15.24 ; 69.213,15.24 ccw(c69.213,16.131) 69.843,15.501 cw(c69.213,16.131) 69.213,15.24
  Bottom Layer w0.254: v1(46.152,35.966) v1(46.152,66.269) ; 46.152,36.273 cw(c45.845,36.273) 46.062,36.056 ccw(c45.845,36.273) 46.152,36.273 ; 46.152,36.273 ccw(c46.458,36.273) 46.242,36.056 cw(c46.458,36.273) 46.152,36.273 ; 46.152,65.962 cw(c46.458,65.962) 46.242,66.179 ccw(c46.458,65.962) 46.152,65.962 ; 46.152,65.962 ccw(c45.845,65.962) 46.062,66.179 cw(c45.845,65.962) 46.152,65.962
ETH_TXD1: P2.48 R9.1 U1.52 | length 90.3
  Top Layer w0.254: v1(46.431,35.179) 46.126,34.874 46.126,31.897 U1.52@46.923,31.1 49.759,28.264 49.759,24.562 57.785,16.535 71.349,16.535 P2.48@72.644,15.24 ; v1(46.888,65.43) 49.2,65.43 51.765,67.996 ; R9.1@51.765,69.063 51.765,67.996 ; 47.195,65.43 cw(c47.195,65.737) 46.978,65.52 ccw(c47.195,65.737) 47.195,65.43 ; 47.195,65.43 ccw(c47.195,65.124) 46.978,65.341 cw(c47.195,65.124) 47.195,65.43 ; 51.765,67.996 cw(c52.38,67.996) 52.043,68.511 ccw(c52.38,67.996) 51.765,67.996 ; 51.765,67.996 ccw(c51.15,67.996) 51.487,68.511 cw(c51.15,67.996) 51.765,67.996 ; 71.58,16.304 cw(c70.517,15.24) 72.021,15.24 ccw(c70.517,15.24) 71.58,16.304 ; 71.58,16.304 ccw(c72.644,17.367) 72.644,15.863 cw(c72.644,17.367) 71.58,16.304 ; 72.014,15.87 cw(c71.384,15.24) 72.275,15.24 ccw(c71.384,15.24) 72.014,15.87 ; 72.014,15.87 ccw(c72.644,16.5) 72.644,15.609 cw(c72.644,16.5) 72.014,15.87 ; 46.126,32.151 ccw(c46.74,32.151) 46.306,31.717 cw(c46.74,32.151) 46.126,32.151
  Bottom Layer w0.254: v1(46.431,35.179) 46.888,35.636 v1(46.888,65.43) ; 46.648,35.396 cw(c46.431,35.613) 46.431,35.306 ccw(c46.431,35.613) 46.648,35.396 ; 46.648,35.396 ccw(c46.865,35.179) 46.558,35.179 cw(c46.865,35.179) 46.648,35.396 ; 46.888,65.124 cw(c47.195,65.124) 46.978,65.341 ccw(c47.195,65.124) 46.888,65.124 ; 46.888,65.124 ccw(c46.582,65.124) 46.799,65.341 cw(c46.582,65.124) 46.888,65.124
ETH_TXEN: P1.50 R7.1 U1.48 | length 89.2
  Top Layer w0.254: P1.50@17.78,12.7 26.975,12.7 42.697,28.423 42.697,30.445 U1.48@43.706,31.453 44.907,32.655 v1(44.907,33.401) ; v1(45.466,66.98) 46.177,66.98 46.685,67.488 R7.1@46.685,69.063 ; 18.671,12.7 cw(c18.671,13.591) 18.041,12.961 ccw(c18.671,13.591) 18.671,12.7 ; 18.671,12.7 ccw(c18.671,11.809) 18.041,12.439 cw(c18.671,11.809) 18.671,12.7 ; 19.284,12.7 cw(c19.284,14.204) 18.221,13.141 ccw(c19.284,14.204) 19.284,12.7 ; 19.284,12.7 ccw(c19.284,11.196) 18.221,12.259 cw(c19.284,11.196) 19.284,12.7 ; 44.907,33.094 cw(c45.214,33.094) 44.997,33.311 ccw(c45.214,33.094) 44.907,33.094 ; 44.907,33.094 ccw(c44.601,33.094) 44.817,33.311 cw(c44.601,33.094) 44.907,33.094 ; 45.773,66.98 cw(c45.773,67.286) 45.556,67.07 ccw(c45.773,67.286) 45.773,66.98 ; 45.773,66.98 ccw(c45.773,66.673) 45.556,66.89 cw(c45.773,66.673) 45.773,66.98 ; 46.685,67.709 cw(c47.912,67.709) 47.044,68.576 ccw(c47.912,67.709) 46.685,67.709 ; 46.685,67.709 ccw(c45.459,67.709) 46.326,68.576 cw(c45.459,67.709) 46.685,67.709
  Bottom Layer w0.254: v1(44.907,33.401) 44.907,43.917 45.415,44.425 45.415,66.98 v1(45.466,66.98) ; 44.907,33.708 cw(c44.601,33.708) 44.817,33.491 ccw(c44.601,33.708) 44.907,33.708 ; 44.907,33.708 ccw(c45.214,33.708) 44.997,33.491 cw(c45.214,33.708) 44.907,33.708 ; 45.415,66.551 cw(c45.895,66.551) 45.556,66.89 ccw(c45.895,66.551) 45.415,66.551
F_CS: P2.6 U1.98 U6.1 | length 65
  Top Layer w0.254: U1.98@47.277,49.166 51.791,53.68 v1(51.791,54.61) ; P2.6@72.644,68.58 U6.1@76.683,68.58 ; 51.791,54.303 cw(c52.097,54.303) 51.88,54.52 ccw(c52.097,54.303) 51.791,54.303 ; 51.791,54.303 ccw(c51.484,54.303) 51.701,54.52 cw(c51.484,54.303) 51.791,54.303 ; 73.535,68.58 cw(c73.535,69.471) 72.905,68.841 ccw(c73.535,69.471) 73.535,68.58 ; 73.535,68.58 ccw(c73.535,67.689) 72.905,68.319 cw(c73.535,67.689) 73.535,68.58 ; 74.148,68.58 cw(c74.148,70.084) 73.085,69.021 ccw(c74.148,70.084) 74.148,68.58 ; 74.148,68.58 ccw(c74.148,67.076) 73.085,68.139 cw(c74.148,67.076) 74.148,68.58 ; 75.542,68.58 cw(c75.542,68.151) 75.846,68.454 ccw(c75.542,68.151) 75.542,68.58 ; 75.542,68.58 ccw(c75.542,69.009) 75.846,68.706 cw(c75.542,69.009) 75.542,68.58
  Bottom Layer w0.254: v1(51.791,54.61) 51.791,67.539 54.153,69.901 71.323,69.901 P2.6@72.644,68.58 ; 51.791,54.917 cw(c51.484,54.917) 51.701,54.7 ccw(c51.484,54.917) 51.791,54.917 ; 51.791,54.917 ccw(c52.097,54.917) 51.88,54.7 cw(c52.097,54.917) 51.791,54.917 ; 71.58,69.644 cw(c70.517,68.58) 72.021,68.58 ccw(c70.517,68.58) 71.58,69.644 ; 71.58,69.644 ccw(c72.644,70.707) 72.644,69.203 cw(c72.644,70.707) 71.58,69.644 ; 72.014,69.21 cw(c71.384,68.58) 72.275,68.58 ccw(c71.384,68.58) 72.014,69.21 ; 72.014,69.21 ccw(c72.644,69.84) 72.644,68.949 cw(c72.644,69.84) 72.014,69.21
FSMC_A16: 2.4'/2.8'LCD.2 P2.42 U1.58 | length 68.7
  Top Layer w0.254: U1.58@49.045,33.221 54.178,28.087 54.178,25.654 55.702,24.13 v1(63.017,24.13) 71.374,24.13 P2.42@72.644,22.86 ; 62.711,24.13 cw(c62.711,23.823) 62.928,24.04 ccw(c62.711,23.823) 62.711,24.13 ; 62.711,24.13 ccw(c62.711,24.437) 62.928,24.22 cw(c62.711,24.437) 62.711,24.13 ; 63.324,24.13 cw(c63.324,24.437) 63.107,24.22 ccw(c63.324,24.437) 63.324,24.13 ; 63.324,24.13 ccw(c63.324,23.823) 63.107,24.04 cw(c63.324,23.823) 63.324,24.13 ; 71.58,23.924 cw(c70.517,22.86) 72.021,22.86 ccw(c70.517,22.86) 71.58,23.924 ; 71.58,23.924 ccw(c72.644,24.987) 72.644,23.483 cw(c72.644,24.987) 71.58,23.924 ; 72.014,23.49 cw(c71.384,22.86) 72.275,22.86 ccw(c71.384,22.86) 72.014,23.49 ; 72.014,23.49 ccw(c72.644,24.12) 72.644,23.229 cw(c72.644,24.12) 72.014,23.49
  Bottom Layer w0.254: v1(63.017,24.13) 63.017,5.004 2.4'/2.8'LCD.2@64.287,3.734 ; 63.017,23.823 cw(c63.324,23.823) 63.107,24.04 ccw(c63.324,23.823) 63.017,23.823 ; 63.017,23.823 ccw(c62.711,23.823) 62.928,24.04 cw(c62.711,23.823) 63.017,23.823 ; 63.16,4.861 cw(c62.033,3.734) 63.627,3.734 ccw(c62.033,3.734) 63.16,4.861 ; 63.16,4.861 ccw(c64.287,5.989) 64.287,4.394 cw(c64.287,5.989) 63.16,4.861 ; 63.594,4.428 cw(c62.9,3.734) 63.881,3.734 ccw(c62.9,3.734) 63.594,4.428 ; 63.594,4.428 ccw(c64.287,5.121) 64.287,4.14 cw(c64.287,5.121) 63.594,4.428
FSMC_D0: 2.4'/2.8'LCD.6 P2.37 U1.61 | length 65.9
  Top Layer w0.254: U1.61@50.105,34.282 56.447,27.94 v1(57.937,27.94) P2.37@70.104,27.94 ; 57.631,27.94 cw(c57.631,27.633) 57.848,27.85 ccw(c57.631,27.633) 57.631,27.94 ; 57.631,27.94 ccw(c57.631,28.247) 57.848,28.03 cw(c57.631,28.247) 57.631,27.94 ; 58.244,27.94 cw(c58.244,28.247) 58.027,28.03 ccw(c58.244,28.247) 58.244,27.94 ; 58.244,27.94 ccw(c58.244,27.633) 58.027,27.85 cw(c58.244,27.633) 58.244,27.94 ; 68.6,27.94 cw(c68.6,26.436) 69.663,27.499 ccw(c68.6,26.436) 68.6,27.94 ; 68.6,27.94 ccw(c68.6,29.444) 69.663,28.381 cw(c68.6,29.444) 68.6,27.94 ; 69.213,27.94 cw(c69.213,27.049) 69.843,27.679 ccw(c69.213,27.049) 69.213,27.94 ; 69.213,27.94 ccw(c69.213,28.831) 69.843,28.201 cw(c69.213,28.831) 69.213,27.94
  Bottom Layer w0.254: v1(57.937,27.94) 57.937,5.004 2.4'/2.8'LCD.6@59.207,3.734 ; 57.937,27.633 cw(c58.244,27.633) 58.027,27.85 ccw(c58.244,27.633) 57.937,27.633 ; 57.937,27.633 ccw(c57.631,27.633) 57.848,27.85 cw(c57.631,27.633) 57.937,27.633 ; 58.08,4.861 cw(c56.953,3.734) 58.547,3.734 ccw(c56.953,3.734) 58.08,4.861 ; 58.08,4.861 ccw(c59.207,5.989) 59.207,4.394 cw(c59.207,5.989) 58.08,4.861 ; 58.514,4.428 cw(c57.82,3.734) 58.801,3.734 ccw(c57.82,3.734) 58.514,4.428 ; 58.514,4.428 ccw(c59.207,5.121) 59.207,4.14 cw(c59.207,5.121) 58.514,4.428
FSMC_D1: 2.4'/2.8'LCD.7 P2.38 U1.62 | length 66.4
  Top Layer w0.254: U1.62@50.459,34.635 55.884,29.21 v1(56.667,29.21) 71.374,29.21 P2.38@72.644,27.94 ; 56.361,29.21 cw(c56.361,28.903) 56.578,29.12 ccw(c56.361,28.903) 56.361,29.21 ; 56.361,29.21 ccw(c56.361,29.517) 56.578,29.3 cw(c56.361,29.517) 56.361,29.21 ; 56.974,29.21 cw(c56.974,29.517) 56.757,29.3 ccw(c56.974,29.517) 56.974,29.21 ; 56.974,29.21 ccw(c56.974,28.903) 56.757,29.12 cw(c56.974,28.903) 56.974,29.21 ; 71.58,29.004 cw(c70.517,27.94) 72.021,27.94 ccw(c70.517,27.94) 71.58,29.004 ; 71.58,29.004 ccw(c72.644,30.067) 72.644,28.563 cw(c72.644,30.067) 71.58,29.004 ; 72.014,28.57 cw(c71.384,27.94) 72.275,27.94 ccw(c71.384,27.94) 72.014,28.57 ; 72.014,28.57 ccw(c72.644,29.2) 72.644,28.309 cw(c72.644,29.2) 72.014,28.57
  Bottom Layer w0.254: 2.4'/2.8'LCD.7@56.667,6.274 v1(56.667,29.21) ; 56.667,7.255 cw(c55.686,7.255) 56.38,6.561 ccw(c55.686,7.255) 56.667,7.255 ; 56.667,7.255 ccw(c57.649,7.255) 56.955,6.561 cw(c57.649,7.255) 56.667,7.255 ; 56.667,7.868 cw(c55.073,7.868) 56.2,6.741 ccw(c55.073,7.868) 56.667,7.868 ; 56.667,7.868 ccw(c58.262,7.868) 57.134,6.741 cw(c58.262,7.868) 56.667,7.868 ; 56.667,28.903 cw(c56.974,28.903) 56.757,29.12 ccw(c56.974,28.903) 56.667,28.903 ; 56.667,28.903 ccw(c56.361,28.903) 56.578,29.12 cw(c56.361,28.903) 56.667,28.903
FSMC_D2: 2.4'/2.8'LCD.8 P2.22 U1.81 | length 82.4
  Top Layer w0.254: v1(52.146,41.275) 52.146,42.015 U1.81@53.287,43.156 59.687,49.555 71.349,49.555 P2.22@72.644,48.26 ; 52.146,41.582 cw(c51.84,41.582) 52.056,41.365 ccw(c51.84,41.582) 52.146,41.582 ; 52.146,41.582 ccw(c52.453,41.582) 52.236,41.365 cw(c52.453,41.582) 52.146,41.582 ; 71.58,49.324 cw(c70.517,48.26) 72.021,48.26 ccw(c70.517,48.26) 71.58,49.324 ; 71.58,49.324 ccw(c72.644,50.387) 72.644,48.883 cw(c72.644,50.387) 71.58,49.324 ; 72.014,48.89 cw(c71.384,48.26) 72.275,48.26 ccw(c71.384,48.26) 72.014,48.89 ; 72.014,48.89 ccw(c72.644,49.52) 72.644,48.629 cw(c72.644,49.52) 72.014,48.89
  Bottom Layer w0.254: v1(52.146,41.275) 56.007,37.414 56.007,11.836 55.397,11.227 55.397,5.004 2.4'/2.8'LCD.8@56.667,3.734 ; 52.363,41.058 cw(c52.58,41.275) 52.273,41.275 ccw(c52.58,41.275) 52.363,41.058 ; 52.363,41.058 ccw(c52.146,40.841) 52.146,41.148 cw(c52.146,40.841) 52.363,41.058 ; 55.54,4.861 cw(c54.413,3.734) 56.007,3.734 ccw(c54.413,3.734) 55.54,4.861 ; 55.54,4.861 ccw(c56.667,5.989) 56.667,4.394 cw(c56.667,5.989) 55.54,4.861 ; 55.974,4.428 cw(c55.28,3.734) 56.261,3.734 ccw(c55.28,3.734) 55.974,4.428 ; 55.974,4.428 ccw(c56.667,5.121) 56.667,4.14 cw(c56.667,5.121) 55.974,4.428
FSMC_D3: 2.4'/2.8'LCD.9 P2.19 U1.82 | length 77.6
  Top Layer w0.254: v1(51.562,40.665) 51.562,42.138 U1.82@52.934,43.509 60.224,50.8 P2.19@70.104,50.8 ; 51.562,40.972 cw(c51.255,40.972) 51.472,40.755 ccw(c51.255,40.972) 51.562,40.972 ; 51.562,40.972 ccw(c51.869,40.972) 51.652,40.755 cw(c51.869,40.972) 51.562,40.972 ; 68.6,50.8 cw(c68.6,49.296) 69.663,50.359 ccw(c68.6,49.296) 68.6,50.8 ; 68.6,50.8 ccw(c68.6,52.304) 69.663,51.241 cw(c68.6,52.304) 68.6,50.8 ; 69.213,50.8 cw(c69.213,49.909) 69.843,50.539 ccw(c69.213,49.909) 69.213,50.8 ; 69.213,50.8 ccw(c69.213,51.691) 69.843,51.061 cw(c69.213,51.691) 69.213,50.8
  Bottom Layer w0.254: v1(51.562,40.665) 55.372,36.855 55.372,12.294 54.127,11.049 2.4'/2.8'LCD.9@54.127,6.274 ; 51.779,40.449 cw(c51.996,40.665) 51.689,40.665 ccw(c51.996,40.665) 51.779,40.449 ; 51.779,40.449 ccw(c51.562,40.232) 51.562,40.538 cw(c51.562,40.232) 51.779,40.449 ; 54.127,7.255 cw(c53.146,7.255) 53.84,6.561 ccw(c53.146,7.255) 54.127,7.255 ; 54.127,7.255 ccw(c55.109,7.255) 54.415,6.561 cw(c55.109,7.255) 54.127,7.255 ; 54.127,7.868 cw(c52.533,7.868) 53.66,6.741 ccw(c52.533,7.868) 54.127,7.868 ; 54.127,7.868 ccw(c55.722,7.868) 54.594,6.741 cw(c55.722,7.868) 54.127,7.868
FSMC_D4: 2.4'/2.8'LCD.10 P1.40 U1.38 | length 80.4
  Top Layer w0.254: P1.40@17.78,25.4 31.217,25.4 v1(37.998,32.182) 37.998,32.817 U1.38@40.17,34.989 ; 18.671,25.4 cw(c18.671,26.291) 18.041,25.661 ccw(c18.671,26.291) 18.671,25.4 ; 18.671,25.4 ccw(c18.671,24.509) 18.041,25.139 cw(c18.671,24.509) 18.671,25.4 ; 19.284,25.4 cw(c19.284,26.904) 18.221,25.841 ccw(c19.284,26.904) 19.284,25.4 ; 19.284,25.4 ccw(c19.284,23.896) 18.221,24.959 cw(c19.284,23.896) 19.284,25.4 ; 37.782,31.965 cw(c37.998,31.748) 37.998,32.055 ccw(c37.998,31.748) 37.782,31.965 ; 37.782,31.965 ccw(c37.565,32.182) 37.871,32.182 cw(c37.565,32.182) 37.782,31.965 ; 37.998,32.488 cw(c37.692,32.488) 37.909,32.272 ccw(c37.692,32.488) 37.998,32.488 ; 37.998,32.488 ccw(c38.305,32.488) 38.088,32.272 cw(c38.305,32.488) 37.998,32.488
  Bottom Layer w0.254: v1@37.96,32.22 v1(37.998,32.182) 52.857,17.323 52.857,5.004 2.4'/2.8'LCD.10@54.127,3.734 ; 38.215,31.965 cw(c38.432,32.182) 38.125,32.182 ccw(c38.432,32.182) 38.215,31.965 ; 38.215,31.965 ccw(c37.998,31.748) 37.998,32.055 cw(c37.998,31.748) 38.215,31.965 ; 53,4.861 cw(c51.873,3.734) 53.467,3.734 ccw(c51.873,3.734) 53,4.861 ; 53,4.861 ccw(c54.127,5.989) 54.127,4.394 cw(c54.127,5.989) 53,4.861 ; 53.434,4.428 cw(c52.74,3.734) 53.721,3.734 ccw(c52.74,3.734) 53.434,4.428 ; 53.434,4.428 ccw(c54.127,5.121) 54.127,4.14 cw(c54.127,5.121) 53.434,4.428
FSMC_D5: 2.4'/2.8'LCD.11 P1.41 U1.39 | length 79.6
  Top Layer w0.254: P1.41@15.24,22.86 16.459,24.079 30.734,24.079 v1(37.706,31.051) 38.583,31.928 38.583,32.694 U1.39@40.524,34.635 ; 15.87,23.49 cw(c15.24,24.12) 15.24,23.229 ccw(c15.24,24.12) 15.87,23.49 ; 15.87,23.49 ccw(c16.5,22.86) 15.609,22.86 cw(c16.5,22.86) 15.87,23.49 ; 16.304,23.924 cw(c15.24,24.987) 15.24,23.483 ccw(c15.24,24.987) 16.304,23.924 ; 16.304,23.924 ccw(c17.367,22.86) 15.863,22.86 cw(c17.367,22.86) 16.304,23.924 ; 37.489,30.835 cw(c37.706,30.618) 37.706,30.924 ccw(c37.706,30.618) 37.489,30.835 ; 37.489,30.835 ccw(c37.273,31.051) 37.579,31.051 cw(c37.273,31.051) 37.489,30.835 ; 37.923,31.268 cw(c37.706,31.485) 37.706,31.178 ccw(c37.706,31.485) 37.923,31.268 ; 37.923,31.268 ccw(c38.14,31.051) 37.833,31.051 cw(c38.14,31.051) 37.923,31.268
  Bottom Layer w0.254: v1(37.706,31.051) 51.587,17.17 2.4'/2.8'LCD.11@51.587,6.274 ; 37.923,30.835 cw(c38.14,31.051) 37.833,31.051 ccw(c38.14,31.051) 37.923,30.835 ; 37.923,30.835 ccw(c37.706,30.618) 37.706,30.924 cw(c37.706,30.618) 37.923,30.835 ; 51.587,7.255 cw(c50.606,7.255) 51.3,6.561 ccw(c50.606,7.255) 51.587,7.255 ; 51.587,7.255 ccw(c52.569,7.255) 51.875,6.561 cw(c52.569,7.255) 51.587,7.255 ; 51.587,7.868 cw(c49.993,7.868) 51.12,6.741 ccw(c49.993,7.868) 51.587,7.868 ; 51.587,7.868 ccw(c53.182,7.868) 52.054,6.741 cw(c53.182,7.868) 51.587,7.868
FSMC_D6: 2.4'/2.8'LCD.12 P1.42 U1.40 | length 78.9
  Top Layer w0.254: P1.42@17.78,22.86 30.341,22.86 v1(37.434,29.953) 39.04,31.559 39.04,32.444 U1.40@40.878,34.282 ; 18.671,22.86 cw(c18.671,23.751) 18.041,23.121 ccw(c18.671,23.751) 18.671,22.86 ; 18.671,22.86 ccw(c18.671,21.969) 18.041,22.599 cw(c18.671,21.969) 18.671,22.86 ; 19.284,22.86 cw(c19.284,24.364) 18.221,23.301 ccw(c19.284,24.364) 19.284,22.86 ; 19.284,22.86 ccw(c19.284,21.356) 18.221,22.419 cw(c19.284,21.356) 19.284,22.86 ; 37.217,29.736 cw(c37.434,29.519) 37.434,29.826 ccw(c37.434,29.519) 37.217,29.736 ; 37.217,29.736 ccw(c37,29.953) 37.307,29.953 cw(c37,29.953) 37.217,29.736 ; 37.65,30.169 cw(c37.434,30.386) 37.434,30.08 ccw(c37.434,30.386) 37.65,30.169 ; 37.65,30.169 ccw(c37.867,29.953) 37.561,29.953 cw(c37.867,29.953) 37.65,30.169
  Bottom Layer w0.254: v1(37.434,29.953) 50.317,17.069 50.317,5.004 2.4'/2.8'LCD.12@51.587,3.734 ; 37.65,29.736 cw(c37.867,29.953) 37.561,29.953 ccw(c37.867,29.953) 37.65,29.736 ; 37.65,29.736 ccw(c37.434,29.519) 37.434,29.826 cw(c37.434,29.519) 37.65,29.736 ; 50.46,4.861 cw(c49.333,3.734) 50.927,3.734 ccw(c49.333,3.734) 50.46,4.861 ; 50.46,4.861 ccw(c51.587,5.989) 51.587,4.394 cw(c51.587,5.989) 50.46,4.861 ; 50.894,4.428 cw(c50.2,3.734) 51.181,3.734 ccw(c50.2,3.734) 50.894,4.428 ; 50.894,4.428 ccw(c51.587,5.121) 51.587,4.14 cw(c51.587,5.121) 50.894,4.428
FSMC_D7: 2.4'/2.8'LCD.13 P1.43 U1.41 | length 78.2
  Top Layer w0.254: P1.43@15.24,20.32 16.535,21.615 29.972,21.615 v1(37.211,28.854) 39.497,31.14 39.497,32.194 U1.41@41.231,33.928 ; 15.87,20.95 cw(c15.24,21.58) 15.24,20.689 ccw(c15.24,21.58) 15.87,20.95 ; 15.87,20.95 ccw(c16.5,20.32) 15.609,20.32 cw(c16.5,20.32) 15.87,20.95 ; 16.304,21.384 cw(c15.24,22.447) 15.24,20.943 ccw(c15.24,22.447) 16.304,21.384 ; 16.304,21.384 ccw(c17.367,20.32) 15.863,20.32 cw(c17.367,20.32) 16.304,21.384 ; 36.994,28.638 cw(c37.211,28.421) 37.211,28.727 ccw(c37.211,28.421) 36.994,28.638 ; 36.994,28.638 ccw(c36.777,28.854) 37.084,28.854 cw(c36.777,28.854) 36.994,28.638 ; 37.428,29.071 cw(c37.211,29.288) 37.211,28.981 ccw(c37.211,29.288) 37.428,29.071 ; 37.428,29.071 ccw(c37.645,28.854) 37.338,28.854 cw(c37.645,28.854) 37.428,29.071
  Bottom Layer w0.254: v1@37.224,28.867 49.047,17.043 2.4'/2.8'LCD.13@49.047,6.274 ; 49.047,7.255 cw(c48.066,7.255) 48.76,6.561 ccw(c48.066,7.255) 49.047,7.255 ; 49.047,7.255 ccw(c50.029,7.255) 49.335,6.561 cw(c50.029,7.255) 49.047,7.255 ; 49.047,7.868 cw(c47.453,7.868) 48.58,6.741 ccw(c47.453,7.868) 49.047,7.868 ; 49.047,7.868 ccw(c50.642,7.868) 49.514,6.741 cw(c50.642,7.868) 49.047,7.868 ; v1@37.211,28.727 cw(c37.211,28.359) 37.471,28.62 ccw(c37.211,28.359) v1@37.211,28.727 ; v1@37.338,28.854 ccw(c37.583,28.854) 37.41,28.681 cw(c37.583,28.854) v1@37.338,28.854
FSMC_D8: 2.4'/2.8'LCD.14 P1.44 U1.42 | length 77.5
  Top Layer w0.254: P1.44@17.78,20.32 29.566,20.32 v1(37.008,27.762) 39.954,30.709 39.954,31.944 U1.42@41.585,33.575 ; 18.671,20.32 cw(c18.671,21.211) 18.041,20.581 ccw(c18.671,21.211) 18.671,20.32 ; 18.671,20.32 ccw(c18.671,19.429) 18.041,20.059 cw(c18.671,19.429) 18.671,20.32 ; 19.284,20.32 cw(c19.284,21.824) 18.221,20.761 ccw(c19.284,21.824) 19.284,20.32 ; 19.284,20.32 ccw(c19.284,18.816) 18.221,19.879 cw(c19.284,18.816) 19.284,20.32 ; 36.791,27.545 cw(c37.008,27.329) 37.008,27.635 ccw(c37.008,27.329) 36.791,27.545 ; 36.791,27.545 ccw(c36.574,27.762) 36.881,27.762 cw(c36.574,27.762) 36.791,27.545 ; 37.225,27.979 cw(c37.008,28.196) 37.008,27.889 ccw(c37.008,28.196) 37.225,27.979 ; 37.225,27.979 ccw(c37.441,27.762) 37.135,27.762 cw(c37.441,27.762) 37.225,27.979
  Bottom Layer w0.254: v1@37.02,27.775 47.803,16.993 47.803,4.978 2.4'/2.8'LCD.14@49.047,3.734 ; 47.92,4.861 cw(c46.793,3.734) 48.387,3.734 ccw(c46.793,3.734) 47.92,4.861 ; 47.92,4.861 ccw(c49.047,5.989) 49.047,4.394 cw(c49.047,5.989) 47.92,4.861 ; 48.354,4.428 cw(c47.66,3.734) 48.641,3.734 ccw(c47.66,3.734) 48.354,4.428 ; 48.354,4.428 ccw(c49.047,5.121) 49.047,4.14 cw(c49.047,5.121) 48.354,4.428 ; v1@37.008,27.635 cw(c37.008,27.267) 37.268,27.527 ccw(c37.008,27.267) v1@37.008,27.635 ; v1@37.135,27.762 ccw(c37.38,27.762) 37.207,27.589 cw(c37.38,27.762) v1@37.135,27.762
FSMC_D9: 2.4'/2.8'LCD.15 P1.45 U1.43 | length 76.8
  Top Layer w0.254: P1.45@15.24,17.78 16.51,19.05 29.159,19.05 v1(36.703,26.594) 40.411,30.302 40.411,31.694 U1.43@41.938,33.221 ; 15.87,18.41 cw(c15.24,19.04) 15.24,18.149 ccw(c15.24,19.04) 15.87,18.41 ; 15.87,18.41 ccw(c16.5,17.78) 15.609,17.78 cw(c16.5,17.78) 15.87,18.41 ; 16.304,18.844 cw(c15.24,19.907) 15.24,18.403 ccw(c15.24,19.907) 16.304,18.844 ; 16.304,18.844 ccw(c17.367,17.78) 15.863,17.78 cw(c17.367,17.78) 16.304,18.844 ; 36.486,26.377 cw(c36.703,26.16) 36.703,26.467 ccw(c36.703,26.16) 36.486,26.377 ; 36.486,26.377 ccw(c36.269,26.594) 36.576,26.594 cw(c36.269,26.594) 36.486,26.377 ; 36.92,26.811 cw(c36.703,27.027) 36.703,26.721 ccw(c36.703,27.027) 36.92,26.811 ; 36.92,26.811 ccw(c37.137,26.594) 36.83,26.594 cw(c37.137,26.594) 36.92,26.811
  Bottom Layer w0.254: v1@36.716,26.607 46.507,16.815 2.4'/2.8'LCD.15@46.507,6.274 ; 46.507,7.255 cw(c45.526,7.255) 46.22,6.561 ccw(c45.526,7.255) 46.507,7.255 ; 46.507,7.255 ccw(c47.489,7.255) 46.795,6.561 cw(c47.489,7.255) 46.507,7.255 ; 46.507,7.868 cw(c44.913,7.868) 46.04,6.741 ccw(c44.913,7.868) 46.507,7.868 ; 46.507,7.868 ccw(c48.102,7.868) 46.974,6.741 cw(c48.102,7.868) 46.507,7.868 ; v1@36.703,26.467 cw(c36.703,26.099) 36.963,26.359 ccw(c36.703,26.099) v1@36.703,26.467 ; v1@36.83,26.594 ccw(c37.075,26.594) 36.902,26.42 cw(c37.075,26.594) v1@36.83,26.594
